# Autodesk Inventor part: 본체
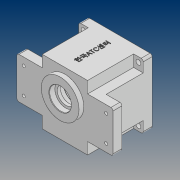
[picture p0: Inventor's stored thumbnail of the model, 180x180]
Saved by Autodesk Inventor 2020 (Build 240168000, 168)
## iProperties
Created: 2020-07
Part Number: 본체
Material: 일반
Document SubType Name: Modeling
Designer: PC312-
Density: 1 g/cm^3
Appearance: 기본값
Author: PC312-
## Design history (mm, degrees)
sketch "스케치1"
  geometry: L1 (-47, 47)-(47, 47); L2 (47, 47)-(47, -47); L3 (47, -47)-(-47, -47); L4 (-47, -47)-(-47, 47); L5 (-47, 47)-(47, -47); L6 (47, 47)-(-47, -47); 1 further point
  constraints: 12 end point, 2 midpoint, 2 parallel, 1 horizontal, 1 perpendicular
  dimensions: "d0" = 94 distance of L1.start L1.end; "d1" = 94 distance of L3.end L1.start
extrude "돌출1" new body sketch "스케치1" stored distance "d2" = 80; taper "d3" = 0 deg
sketch "스케치2"
  geometry: L1 (-47, -47)-(-47, 47) reference; L2 (-47, 30)-(-70, 30); L3 (-70, 30)-(-70, -30); L4 (-70, -30)-(-47, -30); L5 (-47, 30)-(-47, -30); L6 (47, 47)-(47, -47) reference; L7 (47, 30)-(47, -30); L8 (47, -30)-(70, -30); L9 (70, -30)-(70, 30); L10 (70, 30)-(47, 30); 1 further point
  constraints: 16 end point, 4 horizontal, 4 point on line, 3 vertical
  dimensions: "d5" = 70 distance from line of L9 point (0, 0); "d6" = 70 distance from line of point (0, 0) L3; "d7" = 60 distance of L2.end L3.end; "d8" = 60 distance of L8.end L9.end; "d9" = 30 distance from line of point (0, 0) L2; "d10" = 30 distance from line of point (0, 0) L10
extrude "돌출2" join sketch "스케치2" distance "d11" = 13; taper "d12" = 0 deg
sketch "스케치3"
  geometry: L1 (47, 47)-(47, -47) reference; L2 (47, 47)-(33, 47); L3 (33, 47)-(33, 30); L4 (33, 30)-(47, 30); L5 (47, 30)-(47, 47); L6 (47, 30)-(70, 30) reference; L7 (47, -47)-(-47, -47) reference; L8 (47, -47)-(33, -47); L9 (33, -47)-(33, -30); L10 (33, -30)-(47, -30); L11 (47, -30)-(47, -47); L12 (70, -30)-(47, -30) reference; 6 further points
  constraints: 16 end point, 4 parallel, 2 horizontal, 2 horizontal alignment, 2 midpoint, 2 perpendicular
  dimensions: "d13" = 33 distance from line of L3 point (0, 0); "d14" = 33 distance from line of L9 point (0, 0)
extrude "돌출3" cut sketch "스케치3" distance "d15" = 67; taper "d16" = 0 deg
sketch "스케치4"
  geometry: C1 r 43 at (0, 0); 1 further point
  constraints: 1 centre point, 1 coincident
  dimensions: "d17" = 86 diameter of C1
extrude "돌출4" cut sketch "스케치4" distance "d18" = 9; taper "d19" = 0 deg
sketch "스케치5"
  geometry: C1 r 40 at (0, 0); 1 further point
  constraints: 1 centre point, 1 coincident
  dimensions: "d20" = 80 diameter of C1
extrude "돌출5" cut sketch "스케치5" distance "d21" = 62; taper "d22" = 0 deg
sketch "스케치6"
  geometry: C1 r 17.5 at (0, 11); C2 r 11 at (0, -20); A1 r 21 centre (0, 11) between (8.978, -7.984) and (-8.978, -7.984); A2 r 15 centre (0, -20) between (-8.978, -7.984) and (8.978, -7.984); 1 further point
  constraints: 4 centre point, 4 point on circle, 2 coincident, 2 vertical alignment
  dimensions: "d23" = 42 diameter of A1; "d24" = 11 distance of point (0, 0) A1.centre; "d25" = 30 diameter of A2; "d26" = 20 distance of A2.centre point (0, 0); "d27" = 35 diameter of C1; "d28" = 22 diameter of C2
extrude "돌출6" join sketch "스케치6" distance "d29" = 7; taper "d30" = 0 deg
sketch "스케치8"
  geometry: C1 r 27.5 at (0, 11); 1 further point
  constraints: 1 centre point, 1 vertical alignment
  dimensions: "d31" = 55 diameter of C1; "d32" = 11 distance of point (0, 0) C1.centre
extrude "돌출7" join sketch "스케치8" distance "d33" = 7; taper "d34" = 0 deg
sketch "스케치9"
  geometry: L1 (38.5, 47)-(-16.5, 47) reference; L2 (11, 47)-(11, 6.865); L3 (11, 47)-(27, 47); L4 (27, 38.7)-(23.5, 38.7); L5 (27, 47)-(27, 38.7); L6 (23.5, 38.7)-(23.5, 34); L7 (23.5, 34)-(28.5, 34); L8 (28.5, 34)-(28.5, 24); L9 (28.5, 24)-(11, 24); 1 further point
  constraints: 16 end point, 4 vertical, 3 horizontal, 2 point on line, 1 midpoint
  dimensions: "d35" = 11 distance from line of point (0, 0) L2; "d37" = 32 diameter of L5 L2; "d38" = 25 diameter of L6 L2; "d39" = 35 diameter of L8 L2; "d41" = 23 distance between parallel lines of L1 L9; "d42" = 10 distance between parallel lines of L9 L7; "d43" = 8.3 distance between parallel lines of L4 L1
revolve "회전1" sketch "스케치9" stored, may be unused: angle "d44" = 90 deg
sketch "스케치10"
  geometry: C1 r 11 at (0, 0) reference; C2 r 9.5 at (0, 0); 1 further point
  constraints: 1 centre point, 1 coincident
  dimensions: "d45" = 19 diameter of C2
extrude "돌출8" cut sketch "스케치10" distance "d46" = 3; taper "d47" = 0 deg
sketch "스케치11"
  geometry: A1 r 36 centre (0, 0) between (-36, 0) and (36, 0); A2 r 4 centre (-36, 0) between (-37.576, -3.677) and (-37.576, 3.677); A3 r 4 centre (36, 0) between (37.576, 3.677) and (37.576, -3.677); A4 r 1.5 centre (-38.167, 5.055) between (-39.654, 5.252) and (-37.576, 3.677); A5 r 1.5 centre (-38.167, -5.055) between (-37.576, -3.677) and (-39.654, -5.252); A6 r 40 centre (0, 0) between (-39.654, 5.252) and (-39.654, -5.252) reference; A7 r 1.5 centre (38.167, 5.055) between (37.576, 3.677) and (39.654, 5.252); A8 r 1.5 centre (38.167, -5.055) between (39.654, -5.252) and (37.576, -3.677); 1 further point
  constraints: 18 point on circle, 8 tangent, 7 centre point, 2 horizontal alignment, 1 coincident
  dimensions: "d48" = 72 diameter of A1; "d49" = 8 diameter of A2; "d50" = 8 diameter of A3; "d51" = 3 diameter of A4; "d52" = 3 diameter of A5; "d53" = 3 diameter of A7; "d54" = 3 diameter of A8
extrude "돌출9" join sketch "스케치11" distance "d55" = 62; taper "d56" = 0 deg
sketch "스케치12"
  geometry: L1 (-70, -30)-(-70, 30) reference; 3 further points
  dimensions: "d57" = 19 vertical distance of point (0, 0) point (-60, 19); "d58" = 19 vertical distance of point (0, 0) point (-60, -19); "d59" = 10 distance from line of L1 point (-60, -19); "d60" = 10 distance from line of L1 point (-60, 19)
hole "구멍1" sketch "스케치12" at (-60, 19), (-60, -19) diameter "d61" = 4.5; stored, may be unused: countersink angle "d65" = 90 deg, drill point angle "d67" = 118 deg; dims "d62" = 20, "d63" = 10, "d64" = 5, "d66" = 8
fillet "모깎기1" dims "d68" = 3
sketch "스케치13"
  geometry: 3 further points
  dimensions: "d69" = 40 horizontal distance of point (40, 40) point (0, 0); "d70" = 40 horizontal distance of point (40, -40) point (0, 0); "d71" = 40 horizontal distance of point (40, 40) point (0, 0); "d72" = 40 horizontal distance of point (40, -40) point (0, 0)
hole "구멍2" sketch "스케치13" at (40, 40), (40, -40) diameter "d73" = 7; stored, may be unused: countersink angle "d77" = 90 deg, drill point angle "d79" = 118 deg; dims "d74" = 20, "d75" = 10, "d76" = 5, "d78" = 8
sketch "스케치14"
  geometry: A1 r 4 centre (-36, 0) between (-37.576, -3.677) and (-37.576, 3.677) reference; 2 further points
  constraints: 1 coincident
hole "구멍3" sketch "스케치14" at (-36, 0) diameter "d80" = 3.242; stored, may be unused: countersink angle "d84" = 90 deg, drill point angle "d86" = 118 deg; dims "d81" = 7, "d82" = 10, "d83" = 5, "d85" = 9
sketch "스케치15"
  geometry: A1 r 4 centre (36, 0) between (37.576, 3.677) and (37.576, -3.677) reference; 2 further points
  constraints: 1 coincident
hole "구멍4" sketch "스케치15" at (36, 0) diameter "d87" = 3.242; stored, may be unused: countersink angle "d91" = 90 deg, drill point angle "d93" = 118 deg; dims "d88" = 7, "d89" = 10, "d90" = 5, "d92" = 9
fillet "모깎기2" dims "d94" = 3
chamfer "모따기1" distance "d95" = 1; stored, may be unused: second distance "d96" = 2, angle "d97" = 45 deg
chamfer "모따기2" distance "d98" = 0.8; stored, may be unused: second distance "d99" = 2, angle "d100" = 30 deg
node "작업 평면1"
sketch "스케치16"
  geometry: L1 (-77, 80)-(11, 80) reference; 2 further points
  constraints: 1 coincident, 1 other
  dimensions: "d102" = 40 distance from line of L1 point (-33, 40)
feature "엠보싱1" sketch "스케치16" dims "d0" = 94, "d1" = 94, "d103" = 0.5, "d104" = 0
node "솔리드1"
mirror "미러1"
mirror "미러2"
mirror "미러3"
feature "A9D066F2-1C7D-4E18-AEED-F7BC21143FA4" dims "d61" = 4.5, "d62" = 20, "d63" = 10, "d64" = 5, "d65" = 90 deg, "d66" = 8, "d67" = 118 deg
